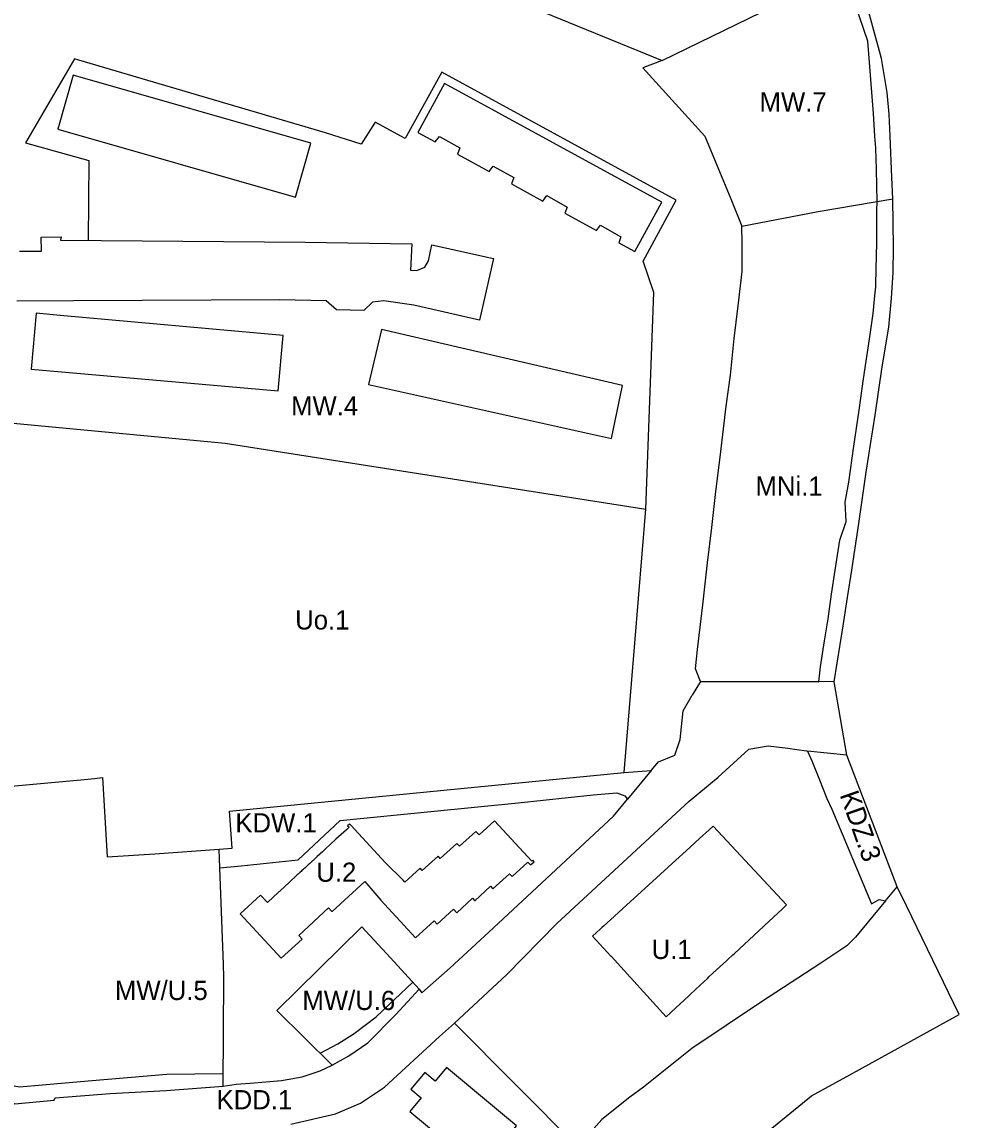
# Model space of a CAD drawing. Extents: x 7426178 to 7427732, y 5548847 to 5550287.
# Drawn here: x 7427197 to 7427416.4, y 5549022.7 to 5549279.8 of the extents above; entities that cross this region are included whole.
import ezdxf

# ---------------------------------------------------------------- set-up
doc = ezdxf.new("R2010")
doc.units = 0
for name, color, linetype in [('linie_rozgraniczajace', 7, 'Continuous'), ('linie_zabudowy_nieprzekraczalne', 7, 'Continuous'), ('linie_zabudowy_obowiazujace', 7, 'Continuous'), ('oznaczenia_przeznaczen', 7, 'Continuous')]:
    doc.layers.add(name, color=color, linetype=linetype)

msp = doc.modelspace()

# ---------------------------------------------------------------- linework, layer by layer
at = {"layer": 'linie_rozgraniczajace'}
for p, q in [((7427398.23, 5549271.32), (7427394.66, 5549284.38)), ((7427399.55, 5549263.32), (7427398.23, 5549271.32)), ((7427401.02, 5549227.11), (7427400.89, 5549238.44)), ((7427401.01, 5549221.15), (7427401.02, 5549227.11)), ((7427344.95, 5549216.52), (7427342.47, 5549223.83)), ((7427400.6, 5549215.14), (7427401.01, 5549221.15)), ((7427399.97, 5549208.33), (7427400.6, 5549215.14)), ((7427398.44, 5549199.1), (7427399.97, 5549208.33)), ((7427396.79, 5549187.73), (7427398.44, 5549199.1)), ((7427395.7, 5549180.89), (7427396.79, 5549187.73)), ((7427394.65, 5549174.39), (7427395.7, 5549180.89)), ((7427393.05, 5549162.97), (7427394.65, 5549174.39)), ((7427391.32, 5549151.5), (7427393.05, 5549162.97)), ((7427390.28, 5549145.09), (7427391.32, 5549151.5)), ((7427389.3, 5549138.45), (7427390.28, 5549145.09)), ((7427387.18, 5549125.33), (7427389.3, 5549138.45)), ((7427337.99, 5549104.1), (7427340.49, 5549134.37)), ((7427390.15, 5549108.13), (7427387.18, 5549125.33)), ((7427390.15, 5549108.13), (7427380.94, 5549109.11)), ((7427401.94, 5549077.31), (7427390.15, 5549108.13)), ((7427344.34, 5549104.52), (7427338.8, 5549097.85))]:
    msp.add_line(p, q, dxfattribs=at)
for points in [[(7427309.2, 5549286.26), (7427346.86, 5549270.85), (7427373.04, 5549283.57), (7427392.05, 5549293.25)], [(7427342.47, 5549223.83), (7427350.16, 5549238.07), (7427295.29, 5549268.09), (7427286.7, 5549252.51), (7427279.66, 5549256.36), (7427276.4, 5549251.23), (7427268.06, 5549253.88), (7427210.28, 5549270.88), (7427209.26, 5549271.18), (7427197.82, 5549251.56), (7427212.64, 5549247.41), (7427212.48, 5549228.68)], [(7427346.86, 5549270.85), (7427342.36, 5549269.08), (7427356.89, 5549253.11)], [(7427400.26, 5549253.11), (7427400.03, 5549258.25), (7427399.55, 5549263.32)], [(7427356.89, 5549253.11), (7427362.94, 5549238.42), (7427365.56, 5549232.04)], [(7427400.89, 5549238.44), (7427400.69, 5549243.41), (7427400.26, 5549253.11)], [(7427365.56, 5549232.04), (7427383.4, 5549235.44), (7427400.89, 5549238.44)], [(7427387.18, 5549125.33), (7427355.85, 5549125.4), (7427354.66, 5549128.4), (7427355.17, 5549132.87), (7427356.41, 5549143.33), (7427357.52, 5549153.22), (7427358.52, 5549161.46), (7427359.35, 5549169.21), (7427360.6, 5549179.29), (7427361.9, 5549189.87), (7427362.89, 5549197.12), (7427363.78, 5549205.68), (7427364.7, 5549213.34), (7427365.66, 5549221.4), (7427365.61, 5549226.16), (7427365.6, 5549228.07), (7427365.56, 5549232.04)], [(7427196.45, 5549226.18), (7427201.6, 5549226.15), (7427201.47, 5549229.45), (7427206.2, 5549229.53), (7427206.01, 5549228.73), (7427263.32, 5549228.26), (7427288.31, 5549227.9), (7427288, 5549221.72), (7427289.48, 5549221.64), (7427291.33, 5549222.44), (7427292.16, 5549223.89), (7427292.98, 5549227.62), (7427307.41, 5549224.48), (7427304.1, 5549209.97), (7427288.77, 5549213.55), (7427281.7, 5549214.53), (7427279.06, 5549214.25), (7427277.01, 5549212.3), (7427270.62, 5549212.39), (7427268.25, 5549214.52), (7427257.35, 5549214.8), (7427209.05, 5549214.51), (7427195.81, 5549214.45)], [(7427343.09, 5549165.77), (7427344.95, 5549216.52)], [(7427189.39, 5549142.47), (7427194.13, 5549185.96), (7427244.55, 5549181.19), (7427343.09, 5549165.77)], [(7427340.49, 5549134.37), (7427343.09, 5549165.77)], [(7427189.39, 5549142.47), (7427190.22, 5549127.54), (7427191.89, 5549100.66), (7427210.8, 5549102.38), (7427213.95, 5549102.67), (7427215.83, 5549102.92)], [(7427355.85, 5549125.4), (7427353.93, 5549122.16)], [(7427337.99, 5549104.1), (7427344.34, 5549104.52), (7427346.06, 5549106.59), (7427349.84, 5549108.18), (7427351.14, 5549111.84), (7427351.79, 5549118.54), (7427353.93, 5549122.16)], [(7427259.91, 5549021.73), (7427270.42, 5549024.12), (7427276.23, 5549026.64), (7427281.91, 5549030.37), (7427294.75, 5549042.28), (7427298.27, 5549045.42), (7427308.26, 5549054.68), (7427310.42, 5549056.67), (7427322.24, 5549068.69), (7427353.21, 5549097.34), (7427360.02, 5549103.01), (7427367.16, 5549109.57), (7427371.74, 5549110.35), (7427376.3, 5549109.78), (7427378.42, 5549109.47), (7427380.71, 5549109.14), (7427380.94, 5549109.11)], [(7427380.94, 5549109.11), (7427381.9, 5549106.81), (7427383.69, 5549102.39), (7427385.47, 5549097.97), (7427386.59, 5549095.53), (7427395.9, 5549073.35), (7427397.73, 5549074.35), (7427399.19, 5549074.01), (7427401.94, 5549077.31)], [(7427215.83, 5549102.92), (7427216.95, 5549084.35), (7427228.09, 5549085.03), (7427243.14, 5549086.1), (7427246.23, 5549086.38), (7427245.55, 5549095.05), (7427337.99, 5549104.1)], [(7427191.89, 5549100.66), (7427188.56, 5549100.49), (7427189.59, 5549080.43), (7427190.95, 5549053.83), (7427189.64, 5549053.39), (7427190.62, 5549035.51), (7427190.82, 5549031.45), (7427191.61, 5549029.08), (7427193.18, 5549027.34), (7427195.3, 5549026.51), (7427204.57, 5549027.34), (7427204.74, 5549027.89), (7427217.64, 5549028.9), (7427230.78, 5549029.62), (7427244.12, 5549030.67)], [(7427243.3, 5549081.75), (7427248.28, 5549082.21), (7427261.66, 5549083.66), (7427271.53, 5549092.88), (7427313.16, 5549097.01), (7427330.76, 5549098.87), (7427336.31, 5549099.3), (7427338.17, 5549098.66), (7427338.8, 5549097.85)], [(7427244.12, 5549030.67), (7427247.15, 5549031.08), (7427250.39, 5549031.31), (7427257.79, 5549031.96), (7427262.61, 5549032.83), (7427266.84, 5549034.25), (7427269.65, 5549035.58), (7427273.54, 5549037.76), (7427277.96, 5549040.82), (7427284.56, 5549047.4), (7427289.98, 5549053.35), (7427290.59, 5549052.46), (7427297.24, 5549058.34), (7427306.28, 5549066.69), (7427310.83, 5549070.9), (7427335.51, 5549093.9), (7427338.8, 5549097.85)], [(7427244.12, 5549030.67), (7427244.28, 5549056.08), (7427244.16, 5549059.18), (7427243.3, 5549081.75), (7427243.14, 5549086.1)], [(7427416.4, 5549047.44), (7427404.09, 5549072.87), (7427401.94, 5549077.31)], [(7427399.19, 5549074.01), (7427392.13, 5549065.52), (7427390.09, 5549063.5), (7427384.02, 5549059.44), (7427369.94, 5549050.26), (7427353.86, 5549039.49), (7427342.52, 5549030.44), (7427339.32, 5549028.06), (7427332.77, 5549022.84), (7427327.03, 5549016.4), (7427298.27, 5549045.42)], [(7427289.98, 5549053.35), (7427283.26, 5549060.65), (7427276.54, 5549067.94), (7427256.67, 5549048.32), (7427269.65, 5549035.58)], [(7427322.79, 5548973.01), (7427353.54, 5549005.3), (7427381.87, 5549028.34), (7427390.86, 5549033.31), (7427416.4, 5549047.44)]]:
    msp.add_lwpolyline(points, dxfattribs=at)
at = {"layer": 'linie_zabudowy_nieprzekraczalne'}
for points in [[(7427397.24, 5549237.81), (7427397.08, 5549245.31), (7427396.9, 5549250.32), (7427396.71, 5549253.09), (7427396.41, 5549258.41), (7427395.04, 5549275.33), (7427392.19, 5549283.75), (7427389.09, 5549291.74)], [(7427355.85, 5549125.4), (7427383.55, 5549125.34), (7427384, 5549128.81), (7427384.92, 5549134.89), (7427385.72, 5549140.1), (7427386.55, 5549145.84), (7427387.39, 5549151.47), (7427388.48, 5549158.53), (7427389.97, 5549162.88), (7427389.73, 5549167.42), (7427390.56, 5549172.07), (7427391.76, 5549180.51), (7427393.01, 5549188.95), (7427394.07, 5549196.26), (7427395.54, 5549206.1), (7427396.3, 5549211.54), (7427396.69, 5549215.68), (7427396.93, 5549217.78), (7427396.94, 5549218.62), (7427397.03, 5549221.63), (7427397.09, 5549225.47), (7427397.19, 5549227.75), (7427397.19, 5549231.58), (7427397.18, 5549235.69), (7427397.22, 5549237.81)], [(7427266.82, 5549038.36), (7427270.97, 5549040.57), (7427274.8, 5549042.96), (7427279.95, 5549046.91), (7427288.5, 5549054.96)]]:
    msp.add_lwpolyline(points, dxfattribs=at)
at = {"layer": 'linie_zabudowy_obowiazujace'}
for p, q in [((7427205.96, 5549211.08), (7427200.29, 5549211.62)), ((7427205.96, 5549211.11), (7427205.96, 5549211.08)), ((7427272.95, 5549090.68), (7427272.95, 5549090.68)), ((7427266.13, 5549084.41), (7427266.14, 5549084.4)), ((7427268.03, 5549086.14), (7427268.02, 5549086.15)), ((7427263.22, 5549081.72), (7427262.99, 5549081.52)), ((7427263.44, 5549081.92), (7427263.22, 5549081.72)), ((7427263.22, 5549081.72), (7427263.22, 5549081.72)), ((7427263.66, 5549082.12), (7427263.44, 5549081.92)), ((7427263.44, 5549081.92), (7427263.44, 5549081.92)), ((7427263.88, 5549082.33), (7427263.66, 5549082.12)), ((7427263.66, 5549082.12), (7427263.66, 5549082.12)), ((7427264.1, 5549082.53), (7427263.88, 5549082.33)), ((7427263.88, 5549082.33), (7427263.88, 5549082.33)), ((7427264.32, 5549082.73), (7427264.1, 5549082.53)), ((7427264.1, 5549082.53), (7427264.1, 5549082.53)), ((7427264.32, 5549082.73), (7427264.32, 5549082.73)), ((7427265.59, 5549083.9), (7427264.77, 5549083.15)), ((7427264.77, 5549083.14), (7427264.77, 5549083.15)), ((7427265.59, 5549083.9), (7427265.59, 5549083.9)), ((7427282.01, 5549082.97), (7427282.01, 5549082.97)), ((7427261.23, 5549079.89), (7427258.27, 5549077.16)), ((7427261.45, 5549080.09), (7427261.23, 5549079.89)), ((7427261.23, 5549079.89), (7427261.23, 5549079.89)), ((7427261.45, 5549080.09), (7427261.45, 5549080.09)), ((7427262.11, 5549080.71), (7427261.9, 5549080.5)), ((7427261.9, 5549080.5), (7427261.9, 5549080.5)), ((7427262.33, 5549080.91), (7427262.11, 5549080.71)), ((7427262.12, 5549080.7), (7427262.11, 5549080.71)), ((7427262.56, 5549081.11), (7427262.33, 5549080.91)), ((7427262.33, 5549080.91), (7427262.34, 5549080.9)), ((7427262.78, 5549081.31), (7427262.56, 5549081.11)), ((7427262.56, 5549081.11), (7427262.56, 5549081.11)), ((7427262.99, 5549081.52), (7427262.78, 5549081.31)), ((7427262.78, 5549081.31), (7427262.78, 5549081.31)), ((7427262.99, 5549081.52), (7427263, 5549081.51)), ((7427258.27, 5549077.16), (7427257.01, 5549076)), ((7427269.6, 5549071.56), (7427277.24, 5549078.59)), ((7427337.72, 5549072.3), (7427335.62, 5549070.38)), ((7427335.62, 5549070.38), (7427333.15, 5549068.13)), ((7427357.85, 5549056.2), (7427360.5, 5549058.66))]:
    msp.add_line(p, q, dxfattribs=at)
for points in [[(7427264.62, 5549251.46), (7427209.01, 5549267.38), (7427205.39, 5549254.76), (7427261, 5549238.84), (7427264.62, 5549251.46)], [(7427295.91, 5549265.4), (7427289.68, 5549253.98), (7427293.72, 5549251.75), (7427294.79, 5549253.01), (7427299.51, 5549250.35), (7427299, 5549248.87), (7427306.35, 5549244.82), (7427307.3, 5549246.07), (7427312.13, 5549243.43), (7427311.64, 5549241.91), (7427318.96, 5549237.89), (7427319.91, 5549239.17), (7427324.65, 5549236.48), (7427324.08, 5549235.07), (7427331.48, 5549231.01), (7427332.49, 5549232.24), (7427337.23, 5549229.55), (7427336.75, 5549228.11), (7427340.5, 5549226.05), (7427346.83, 5549237.64), (7427295.91, 5549265.4)], [(7427200.29, 5549211.62), (7427199.14, 5549198.55), (7427257.01, 5549193.45), (7427258.13, 5549206.44), (7427205.96, 5549211.11)], [(7427281.14, 5549207.82), (7427278.11, 5549194.96), (7427335, 5549182.32), (7427337.64, 5549194.69), (7427281.14, 5549207.82)], [(7427273.69, 5549092.01), (7427273.25, 5549091.62), (7427273.58, 5549091.26), (7427272.95, 5549090.68)], [(7427282.01, 5549083.03), (7427274.06, 5549091.67), (7427273.75, 5549092.01)], [(7427311.74, 5549079.71), (7427315.47, 5549083.12), (7427316.08, 5549082.45), (7427316.89, 5549083.2), (7427316.59, 5549083.53), (7427316.34, 5549083.29), (7427307.65, 5549092.79), (7427304.01, 5549089.46), (7427303.24, 5549090.31), (7427299.4, 5549086.8), (7427298.81, 5549087.44), (7427294.95, 5549083.91), (7427294.41, 5549084.51), (7427290.71, 5549081.13), (7427290.21, 5549081.67), (7427286.66, 5549078.42), (7427286.22, 5549078.9), (7427282.04, 5549083)], [(7427272.95, 5549090.68), (7427270.52, 5549088.45), (7427269.34, 5549087.36), (7427268.02, 5549086.15)], [(7427272.95, 5549090.68), (7427272.95, 5549090.68)], [(7427376, 5549073.13), (7427358.84, 5549091.54), (7427357.9, 5549090.69), (7427355.61, 5549088.6), (7427353.34, 5549086.53), (7427349.22, 5549082.78), (7427342.83, 5549076.96), (7427337.72, 5549072.3)], [(7427266.13, 5549084.41), (7427265.77, 5549084.07), (7427265.59, 5549083.9)], [(7427268.02, 5549086.15), (7427267.33, 5549085.51), (7427266.13, 5549084.41)], [(7427266.14, 5549084.4), (7427266.13, 5549084.41)], [(7427268.02, 5549086.15), (7427268.03, 5549086.14)], [(7427263.22, 5549081.72), (7427263.22, 5549081.72)], [(7427263.44, 5549081.92), (7427263.44, 5549081.92)], [(7427263.66, 5549082.12), (7427263.66, 5549082.12)], [(7427263.88, 5549082.33), (7427263.88, 5549082.33)], [(7427264.1, 5549082.53), (7427264.1, 5549082.53)], [(7427264.77, 5549083.15), (7427264.54, 5549082.94), (7427264.32, 5549082.73)], [(7427264.32, 5549082.73), (7427264.32, 5549082.73)], [(7427264.77, 5549083.15), (7427264.77, 5549083.14)], [(7427265.59, 5549083.9), (7427265.59, 5549083.9)], [(7427261.23, 5549079.89), (7427261.23, 5549079.89)], [(7427261.9, 5549080.5), (7427261.67, 5549080.3), (7427261.45, 5549080.09)], [(7427261.45, 5549080.09), (7427261.45, 5549080.09)], [(7427261.9, 5549080.5), (7427261.9, 5549080.5)], [(7427262.11, 5549080.71), (7427262.12, 5549080.7)], [(7427262.34, 5549080.9), (7427262.33, 5549080.91)], [(7427262.56, 5549081.11), (7427262.56, 5549081.11)], [(7427262.78, 5549081.31), (7427262.78, 5549081.31)], [(7427263, 5549081.51), (7427262.99, 5549081.52)], [(7427298.78, 5549071.26), (7427302.5, 5549074.66), (7427303.04, 5549074.07), (7427306.72, 5549077.44), (7427307.26, 5549076.84), (7427311.13, 5549080.37), (7427311.74, 5549079.71)], [(7427258.27, 5549077.16), (7427258.27, 5549077.16)], [(7427277.24, 5549078.59), (7427281.05, 5549074.16), (7427289.1, 5549065.36), (7427293.47, 5549069.35)], [(7427257.01, 5549076), (7427254.45, 5549073.65), (7427252.84, 5549075.4), (7427248.1, 5549071.03), (7427257.71, 5549060.59), (7427262.58, 5549065.07), (7427261.8, 5549065.92), (7427268.8, 5549072.36), (7427269.54, 5549071.56)], [(7427257.01, 5549076), (7427257.01, 5549076)], [(7427293.47, 5549069.35), (7427294.2, 5549068.56), (7427298.04, 5549072.07), (7427298.78, 5549071.26)], [(7427360.5, 5549058.66), (7427361.92, 5549059.98), (7427362.27, 5549060.3), (7427363.44, 5549061.39), (7427363.79, 5549061.72), (7427370.6, 5549068.06), (7427370.84, 5549068.27), (7427375.07, 5549072.2), (7427375.35, 5549072.46), (7427376, 5549073.07)], [(7427335.62, 5549070.38), (7427335.62, 5549070.38)], [(7427332.85, 5549067.86), (7427332.43, 5549067.48), (7427331.43, 5549066.57), (7427330.59, 5549065.8), (7427334.91, 5549061.07)], [(7427333.15, 5549068.13), (7427333.15, 5549068.13), (7427332.85, 5549067.86)], [(7427334.91, 5549061.07), (7427334.91, 5549061.07), (7427334.92, 5549061.06)], [(7427334.92, 5549061.06), (7427347.85, 5549046.9), (7427348.83, 5549047.81), (7427349.11, 5549048.07), (7427353.07, 5549051.75), (7427353.44, 5549052.1)], [(7427355.81, 5549054.3), (7427357.5, 5549055.87), (7427357.85, 5549056.2)], [(7427357.85, 5549056.2), (7427357.85, 5549056.2)], [(7427353.44, 5549052.1), (7427353.44, 5549052.1), (7427355.81, 5549054.3)], [(7427193.09, 5549031.1), (7427196.43, 5549030.48), (7427204.46, 5549031.16), (7427212.47, 5549031.85), (7427230.95, 5549033.41), (7427243.99, 5549033.59)], [(7427296.4, 5549034.97), (7427293.76, 5549031.79), (7427291.29, 5549033.85), (7427288.01, 5549029.9), (7427290.45, 5549027.87), (7427287.83, 5549024.71), (7427304.26, 5549011.07), (7427312.8, 5549021.35), (7427296.4, 5549034.97)]]:
    msp.add_lwpolyline(points, dxfattribs=at)
for centre, start, end in [((7427273.72, 5549092.04), 221.7845, 312.625), ((7427282.04, 5549083), 132.625, 222.6081), ((7427269.57, 5549071.53), 42.6081, 132.8524), ((7427376.03, 5549073.1), 132.9907, 222.9148)]:
    msp.add_arc(centre, 0.045, start, end, dxfattribs=at)

# ---------------------------------------------------------------- texts
at = {"layer": 'oznaczenia_przeznaczen'}
for s, p in [('MW.7', (7427369.7, 5549258.87)), ('MW.4', (7427260, 5549187.7)), ('MNi.1', (7427368.74, 5549168.9)), ('Uo.1', (7427260.96, 5549137.57)), ('KDW.1', (7427246.96, 5549090.06)), ('U.2', (7427265.91, 5549078.49)), ('U.1', (7427344.42, 5549060.41)), ('MW/U.5', (7427218.76, 5549050.81)), ('MW/U.6', (7427262.65, 5549048.47)), ('KDD.1', (7427242.55, 5549025.22))]:
    msp.add_text(s, height=4.5, dxfattribs=at).set_placement(p)
msp.add_text('KDZ.3', height=4.5, rotation=289.4035, dxfattribs=at).set_placement((7427388.41, 5549098.87))

doc.saveas('drawing.dxf')
